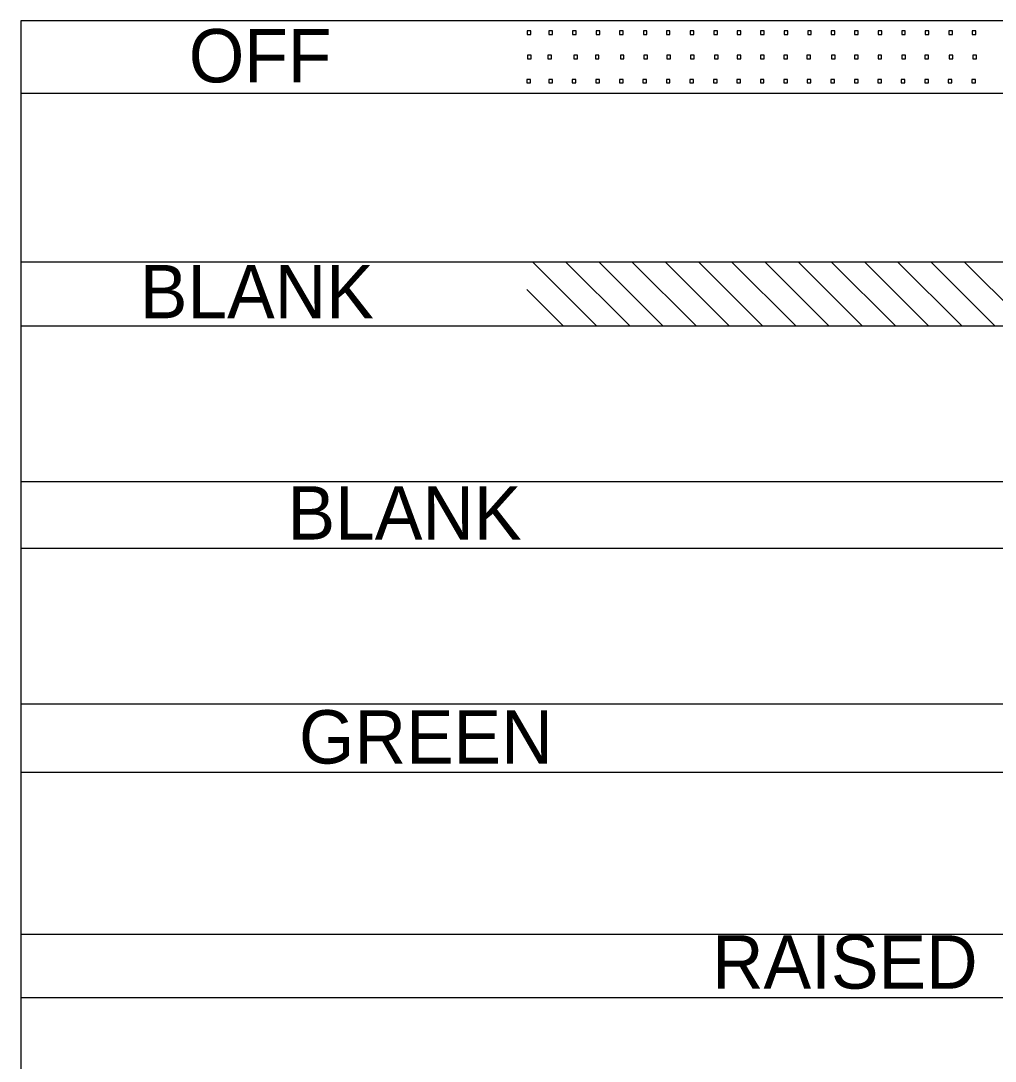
# Model space of a CAD drawing. Extents: x 10000 to 10825, y 10000 to 10530.
# Drawn here: x 10490.2 to 10554.1, y 10117 to 10185.2 of the extents above; entities that cross this region are included whole.
import ezdxf

# ---------------------------------------------------------------- set-up
doc = ezdxf.new("R2010")
doc.units = 0
doc.layers.add('Default', color=7, linetype='Continuous')
doc.layers.add('TextStructures', color=7, linetype='Continuous')

msp = doc.modelspace()

# ---------------------------------------------------------------- linework, layer by layer
at = {"layer": 'Default'}
for p, q in [((10784.11, 10185.22), (10490.187, 10185.22)), ((10490.187, 10185.22), (10490.187, 10048.682)), ((10490.187, 10180.482), (10784.11, 10180.482)), ((10490.187, 10169.414), (10784.11, 10169.414)), ((10523.742, 10169.414), (10527.948, 10165.202)), ((10525.92, 10169.414), (10530.127, 10165.202)), ((10528.099, 10169.414), (10532.305, 10165.202)), ((10530.277, 10169.414), (10534.484, 10165.202)), ((10532.456, 10169.414), (10536.662, 10165.202)), ((10534.634, 10169.414), (10538.841, 10165.202)), ((10536.813, 10169.414), (10541.019, 10165.202)), ((10538.991, 10169.414), (10543.198, 10165.202)), ((10541.169, 10169.414), (10545.376, 10165.202)), ((10543.348, 10169.414), (10547.555, 10165.202)), ((10545.526, 10169.414), (10549.733, 10165.202)), ((10547.705, 10169.414), (10551.912, 10165.202)), ((10549.883, 10169.414), (10554.09, 10165.202)), ((10552.062, 10169.414), (10556.269, 10165.202)), ((10523.377, 10167.598), (10525.77, 10165.202)), ((10490.187, 10165.202), (10784.11, 10165.202)), ((10490.187, 10154.98), (10784.11, 10154.98)), ((10490.187, 10150.62), (10784.11, 10150.62)), ((10490.187, 10140.399), (10784.11, 10140.399)), ((10490.187, 10135.911), (10784.11, 10135.911)), ((10490.187, 10125.289), (10784.11, 10125.289)), ((10490.187, 10121.141), (10784.11, 10121.141))]:
    msp.add_line(p, q, dxfattribs=at)
for points in [[(10523.633, 10184.317), (10523.633, 10184.555), (10523.397, 10184.554), (10523.397, 10184.317), (10523.633, 10184.317)], [(10525.059, 10184.317), (10525.059, 10184.555), (10524.822, 10184.554), (10524.822, 10184.317), (10525.059, 10184.317)], [(10526.622, 10184.317), (10526.622, 10184.555), (10526.386, 10184.554), (10526.386, 10184.317), (10526.622, 10184.317)], [(10528.168, 10184.317), (10528.168, 10184.555), (10527.931, 10184.554), (10527.931, 10184.317), (10528.168, 10184.317)], [(10529.695, 10184.317), (10529.695, 10184.555), (10529.459, 10184.554), (10529.459, 10184.317), (10529.695, 10184.317)], [(10531.259, 10184.317), (10531.259, 10184.555), (10531.023, 10184.554), (10531.023, 10184.317), (10531.259, 10184.317)], [(10532.768, 10184.317), (10532.768, 10184.555), (10532.532, 10184.554), (10532.532, 10184.317), (10532.768, 10184.317)], [(10534.332, 10184.317), (10534.332, 10184.555), (10534.095, 10184.554), (10534.095, 10184.317), (10534.332, 10184.317)], [(10535.878, 10184.317), (10535.878, 10184.555), (10535.641, 10184.554), (10535.641, 10184.317), (10535.878, 10184.317)], [(10537.423, 10184.317), (10537.423, 10184.555), (10537.187, 10184.554), (10537.187, 10184.317), (10537.423, 10184.317)], [(10538.951, 10184.317), (10538.951, 10184.555), (10538.714, 10184.554), (10538.714, 10184.317), (10538.951, 10184.317)], [(10540.496, 10184.317), (10540.496, 10184.555), (10540.26, 10184.554), (10540.26, 10184.317), (10540.496, 10184.317)], [(10542.042, 10184.317), (10542.042, 10184.555), (10541.805, 10184.554), (10541.805, 10184.317), (10542.042, 10184.317)], [(10543.587, 10184.317), (10543.587, 10184.555), (10543.351, 10184.554), (10543.351, 10184.317), (10543.587, 10184.317)], [(10545.115, 10184.317), (10545.115, 10184.555), (10544.878, 10184.554), (10544.878, 10184.317), (10545.115, 10184.317)], [(10546.66, 10184.317), (10546.66, 10184.555), (10546.424, 10184.554), (10546.424, 10184.317), (10546.66, 10184.317)], [(10548.206, 10184.317), (10548.206, 10184.555), (10547.969, 10184.554), (10547.969, 10184.317), (10548.206, 10184.317)], [(10549.751, 10184.317), (10549.751, 10184.555), (10549.515, 10184.554), (10549.515, 10184.317), (10549.751, 10184.317)], [(10551.297, 10184.317), (10551.297, 10184.555), (10551.06, 10184.554), (10551.06, 10184.317), (10551.297, 10184.317)], [(10552.824, 10184.317), (10552.824, 10184.555), (10552.588, 10184.554), (10552.588, 10184.317), (10552.824, 10184.317)], [(10523.661, 10182.728), (10523.661, 10182.967), (10523.424, 10182.966), (10523.424, 10182.728), (10523.661, 10182.728)], [(10524.989, 10182.728), (10524.989, 10182.967), (10524.752, 10182.966), (10524.752, 10182.728), (10524.989, 10182.728)], [(10526.707, 10182.728), (10526.707, 10182.967), (10526.471, 10182.966), (10526.471, 10182.728), (10526.707, 10182.728)], [(10528.113, 10182.728), (10528.113, 10182.967), (10527.877, 10182.966), (10527.877, 10182.728), (10528.113, 10182.728)], [(10529.754, 10182.728), (10529.754, 10182.967), (10529.517, 10182.966), (10529.517, 10182.728), (10529.754, 10182.728)], [(10531.29, 10182.728), (10531.29, 10182.967), (10531.054, 10182.966), (10531.054, 10182.728), (10531.29, 10182.728)], [(10532.801, 10182.728), (10532.801, 10182.967), (10532.564, 10182.966), (10532.564, 10182.728), (10532.801, 10182.728)], [(10534.363, 10182.728), (10534.363, 10182.967), (10534.127, 10182.966), (10534.127, 10182.728), (10534.363, 10182.728)], [(10535.926, 10182.728), (10535.926, 10182.967), (10535.689, 10182.966), (10535.689, 10182.728), (10535.926, 10182.728)], [(10537.41, 10182.728), (10537.41, 10182.967), (10537.173, 10182.966), (10537.173, 10182.728), (10537.41, 10182.728)], [(10538.946, 10182.728), (10538.946, 10182.967), (10538.71, 10182.966), (10538.71, 10182.728), (10538.946, 10182.728)], [(10540.483, 10182.728), (10540.483, 10182.967), (10540.246, 10182.966), (10540.246, 10182.728), (10540.483, 10182.728)], [(10541.993, 10182.728), (10541.993, 10182.967), (10541.757, 10182.966), (10541.757, 10182.728), (10541.993, 10182.728)], [(10543.608, 10182.728), (10543.608, 10182.967), (10543.371, 10182.966), (10543.371, 10182.728), (10543.608, 10182.728)], [(10545.118, 10182.728), (10545.118, 10182.967), (10544.881, 10182.966), (10544.881, 10182.728), (10545.118, 10182.728)], [(10546.655, 10182.728), (10546.655, 10182.967), (10546.418, 10182.966), (10546.418, 10182.728), (10546.655, 10182.728)], [(10548.217, 10182.728), (10548.217, 10182.967), (10547.98, 10182.966), (10547.98, 10182.728), (10548.217, 10182.728)], [(10549.727, 10182.728), (10549.727, 10182.967), (10549.491, 10182.966), (10549.491, 10182.728), (10549.727, 10182.728)], [(10551.316, 10182.728), (10551.316, 10182.967), (10551.079, 10182.966), (10551.079, 10182.728), (10551.316, 10182.728)], [(10552.878, 10182.728), (10552.878, 10182.967), (10552.642, 10182.966), (10552.642, 10182.728), (10552.878, 10182.728)], [(10523.622, 10181.14), (10523.622, 10181.379), (10523.386, 10181.378), (10523.386, 10181.14), (10523.622, 10181.14)], [(10525.057, 10181.14), (10525.057, 10181.379), (10524.82, 10181.378), (10524.82, 10181.14), (10525.057, 10181.14)], [(10526.601, 10181.14), (10526.601, 10181.379), (10526.364, 10181.378), (10526.364, 10181.14), (10526.601, 10181.14)], [(10528.145, 10181.14), (10528.145, 10181.379), (10527.909, 10181.378), (10527.909, 10181.14), (10528.145, 10181.14)], [(10529.69, 10181.14), (10529.69, 10181.379), (10529.453, 10181.378), (10529.453, 10181.14), (10529.69, 10181.14)], [(10531.225, 10181.14), (10531.225, 10181.379), (10530.988, 10181.378), (10530.988, 10181.14), (10531.225, 10181.14)], [(10532.769, 10181.14), (10532.769, 10181.379), (10532.533, 10181.378), (10532.533, 10181.14), (10532.769, 10181.14)], [(10534.304, 10181.14), (10534.304, 10181.379), (10534.068, 10181.378), (10534.068, 10181.14), (10534.304, 10181.14)], [(10535.858, 10181.14), (10535.858, 10181.379), (10535.621, 10181.378), (10535.621, 10181.14), (10535.858, 10181.14)], [(10537.402, 10181.14), (10537.402, 10181.379), (10537.165, 10181.378), (10537.165, 10181.14), (10537.402, 10181.14)], [(10538.937, 10181.14), (10538.937, 10181.379), (10538.701, 10181.378), (10538.701, 10181.14), (10538.937, 10181.14)], [(10540.482, 10181.14), (10540.482, 10181.379), (10540.245, 10181.378), (10540.245, 10181.14), (10540.482, 10181.14)], [(10542.017, 10181.14), (10542.017, 10181.379), (10541.78, 10181.378), (10541.78, 10181.14), (10542.017, 10181.14)], [(10543.552, 10181.14), (10543.552, 10181.379), (10543.315, 10181.378), (10543.315, 10181.14), (10543.552, 10181.14)], [(10545.105, 10181.14), (10545.105, 10181.379), (10544.869, 10181.378), (10544.869, 10181.14), (10545.105, 10181.14)], [(10546.65, 10181.14), (10546.65, 10181.379), (10546.413, 10181.378), (10546.413, 10181.14), (10546.65, 10181.14)], [(10548.176, 10181.14), (10548.176, 10181.379), (10547.939, 10181.378), (10547.939, 10181.14), (10548.176, 10181.14)], [(10549.729, 10181.14), (10549.729, 10181.379), (10549.492, 10181.378), (10549.492, 10181.14), (10549.729, 10181.14)], [(10551.264, 10181.14), (10551.264, 10181.379), (10551.028, 10181.378), (10551.028, 10181.14), (10551.264, 10181.14)], [(10552.818, 10181.14), (10552.818, 10181.379), (10552.581, 10181.378), (10552.581, 10181.14), (10552.818, 10181.14)]]:
    msp.add_lwpolyline(points, dxfattribs=at)

# ---------------------------------------------------------------- texts
at = {"layer": 'TextStructures'}
for s, p in [('OFF', (10501.207, 10181.18)), ('BLANK', (10497.995, 10165.701)), ('BLANK', (10507.684, 10151.182)), ('GREEN', (10508.435, 10136.482)), ('RAISED', (10535.527, 10121.711))]:
    msp.add_text(s, height=3.5, rotation=0.00072, dxfattribs=at).set_placement(p)

doc.saveas('drawing.dxf')
